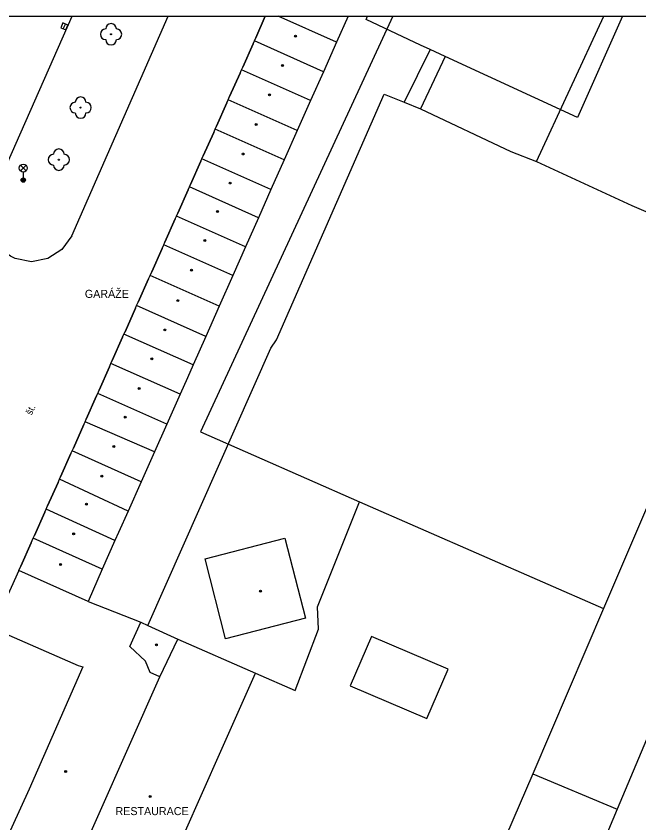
# Model space of a CAD drawing. Extents: x -596024 to -594475, y -1163820 to -1161957.
# Drawn here: x -595647.8 to -595589.5, y -1162032.5 to -1161956.9 of the extents above; entities that cross this region are included whole.
import ezdxf

# ---------------------------------------------------------------- set-up
doc = ezdxf.new("R2010")
doc.units = 0
for name, color, linetype in [('Level 10', 7, 'Continuous'), ('Level 11', 7, 'Continuous'), ('Level 22', 7, 'Continuous'), ('Level 27', 7, 'Continuous'), ('Level 33', 7, 'Continuous'), ('Level 39', 7, 'Continuous'), ('Level 40', 7, 'Continuous'), ('Level 41', 7, 'Continuous'), ('Level 5', 7, 'Continuous'), ('Level 6', 7, 'Continuous'), ('Level 7', 7, 'Continuous'), ('Vrstva 63', 7, 'Continuous')]:
    doc.layers.add(name, color=color, linetype=linetype)

msp = doc.modelspace()

# ---------------------------------------------------------------- linework, layer by layer
at = {"layer": 'Level 10'}
for p, q in [((-595650.28, -1161974.39), (-595642.564, -1161956.88)), ((-595642.59, -1161977.48), (-595633.561, -1161956.88))]:
    msp.add_line(p, q, dxfattribs=at)
msp.add_lwpolyline([(-595642.59, -1161977.48), (-595643.51, -1161978.75), (-595644.83, -1161979.59), (-595646.37, -1161979.89), (-595647.9, -1161979.59), (-595648.34, -1161979.38), (-595649.22, -1161978.74), (-595650.13, -1161977.46), (-595650.5, -1161975.94), (-595650.28, -1161974.39)], dxfattribs=at)
at = {"layer": 'Level 11'}
for p, q in [((-595615, -1161957.19), (-595614.862, -1161956.88)), ((-595599.04, -1161970.51), (-595592.74, -1161956.88))]:
    msp.add_line(p, q, dxfattribs=at)
for points in [[(-595612.513, -1161956.88), (-595630.53, -1161995.84), (-595615.63, -1162002.38), (-595592.77, -1162012.4)], [(-595590.97, -1161956.88), (-595595.2, -1161966.37), (-595607.6, -1161960.65)], [(-595609.02, -1161960), (-595609.9, -1161959.59), (-595615, -1161957.19)], [(-595609.02, -1161960), (-595611.45, -1161964.95)], [(-595607.6, -1161960.65), (-595609.02, -1161960)], [(-595607.6, -1161960.65), (-595609.9, -1161965.58)], [(-595623.92, -1161988), (-595623.41, -1161987.22), (-595613.31, -1161964.2), (-595611.45, -1161964.95)], [(-595611.45, -1161964.95), (-595609.9, -1161965.58)], [(-595609.9, -1161965.58), (-595601.46, -1161969.58), (-595599.04, -1161970.51), (-595590.11, -1161974.62), (-595578.69, -1161979.52), (-595592.77, -1162012.4), (-595599.4, -1162027.88), (-595603.12, -1162036.57)], [(-595635.47, -1162013.97), (-595623.92, -1161988)], [(-595625.37, -1162018.45), (-595621.67, -1162020.07), (-595619.47, -1162014.34), (-595619.57, -1162012.22), (-595615.63, -1162002.38)], [(-595614.49, -1162015.02), (-595616.5, -1162019.65), (-595609.31, -1162022.71)], [(-595609.31, -1162022.71), (-595607.31, -1162018.08), (-595614.49, -1162015.02)], [(-595599.4, -1162027.88), (-595591.49, -1162031.19)]]:
    msp.add_lwpolyline(points, dxfattribs=at)
at = {"layer": 'Level 22'}
for centre in [(-595638.91, -1161958.58), (-595641.76, -1161965.45), (-595643.8, -1161970.33)]:
    msp.add_circle(centre, 0.05, dxfattribs=at)
for centre, start, end in [((-595638.91, -1161958.08), 0, 180), ((-595639.41, -1161958.58), 90, 270), ((-595638.41, -1161958.58), 270, 90), ((-595638.91, -1161959.08), 180, 0), ((-595641.76, -1161964.95), 0, 180), ((-595642.26, -1161965.45), 90, 270), ((-595641.26, -1161965.45), 270, 90), ((-595641.76, -1161965.95), 180, 0), ((-595644.3, -1161970.33), 90, 270), ((-595643.8, -1161969.83), 0, 180), ((-595643.3, -1161970.33), 270, 90), ((-595643.8, -1161970.83), 180, 0)]:
    msp.add_arc(centre, 0.5, start, end, dxfattribs=at)
at = {"layer": 'Level 27'}
msp.add_line((-595643.38, -1161958.079), (-595643.18, -1161957.621), dxfattribs=at)
msp.add_lwpolyline([(-595643.151, -1161958.179), (-595642.951, -1161957.721), (-595643.409, -1161957.521), (-595643.609, -1161957.979)], close=True, dxfattribs=at)
at = {"layer": 'Level 33'}
for p, q in [((-595647.395, -1161971.38), (-595646.865, -1161970.85)), ((-595647.395, -1161970.85), (-595646.865, -1161971.38)), ((-595647.13, -1161971.49), (-595647.13, -1161972.24))]:
    msp.add_line(p, q, dxfattribs=at)
for centre, radius in [((-595647.13, -1161971.115), 0.375), ((-595647.13, -1161972.24), 0.2), ((-595647.13, -1161972.24), 0.145), ((-595647.13, -1161972.24), 0.0876)]:
    msp.add_circle(centre, radius, dxfattribs=at)
at = {"layer": 'Level 39'}
for centre, radius in [((-595621.63, -1161958.76), 0.09), ((-595621.63, -1161958.76), 0.0398), ((-595622.85, -1161961.5), 0.09), ((-595622.85, -1161961.5), 0.0398), ((-595624.07, -1161964.26), 0.09), ((-595624.07, -1161964.26), 0.0398), ((-595625.3, -1161967.03), 0.09), ((-595625.3, -1161967.03), 0.0398), ((-595626.53, -1161969.8), 0.09), ((-595626.53, -1161969.8), 0.0398), ((-595627.74, -1161972.52), 0.09), ((-595627.74, -1161972.52), 0.0398), ((-595628.93, -1161975.19), 0.09), ((-595628.93, -1161975.19), 0.0398), ((-595630.13, -1161977.9), 0.09), ((-595630.13, -1161977.9), 0.0398), ((-595631.37, -1161980.68), 0.09), ((-595631.37, -1161980.68), 0.0398), ((-595632.64, -1161983.54), 0.09), ((-595632.64, -1161983.54), 0.0398), ((-595633.86, -1161986.29), 0.09), ((-595633.86, -1161986.29), 0.0398), ((-595635.08, -1161988.99), 0.09), ((-595635.08, -1161988.99), 0.0398), ((-595636.28, -1161991.78), 0.09), ((-595636.28, -1161991.78), 0.0398), ((-595637.57, -1161994.45), 0.09), ((-595637.57, -1161994.45), 0.0398), ((-595638.64, -1161997.22), 0.09), ((-595638.64, -1161997.22), 0.0398), ((-595639.77, -1161999.99), 0.09), ((-595639.77, -1161999.99), 0.0398), ((-595641.22, -1162002.62), 0.09), ((-595641.22, -1162002.62), 0.0398), ((-595642.41, -1162005.39), 0.09), ((-595642.41, -1162005.39), 0.0398), ((-595643.63, -1162008.27), 0.09), ((-595643.63, -1162008.27), 0.0398), ((-595624.91, -1162010.76), 0.09), ((-595624.91, -1162010.76), 0.0398), ((-595634.66, -1162015.8), 0.09), ((-595634.66, -1162015.8), 0.0398), ((-595643.16, -1162027.67), 0.09), ((-595643.16, -1162027.67), 0.0398), ((-595635.24, -1162030.01), 0.09), ((-595635.24, -1162030.01), 0.0398)]:
    msp.add_circle(centre, radius, dxfattribs=at)
at = {"layer": 'Level 5'}
for p, q in [((-595625.35, -1161958.92), (-595624.451, -1161956.88)), ((-595617.77, -1161959.31), (-595623.237, -1161956.88)), ((-595616.685, -1161956.88), (-595617.77, -1161959.31))]:
    msp.add_line(p, q, dxfattribs=at)
for points in [[(-595625.6, -1161959.47), (-595625.48, -1161959.21)], [(-595625.48, -1161959.21), (-595625.35, -1161958.92)], [(-595619, -1161962.09), (-595625.48, -1161959.21)], [(-595617.77, -1161959.31), (-595619, -1161962.09)], [(-595626.57, -1161961.66), (-595625.6, -1161959.47)], [(-595626.69, -1161961.92), (-595626.57, -1161961.66)], [(-595627.8, -1161964.42), (-595626.82, -1161962.23)], [(-595626.82, -1161962.23), (-595626.69, -1161961.92)], [(-595620.21, -1161964.8), (-595626.69, -1161961.92)], [(-595619, -1161962.09), (-595620.21, -1161964.8)], [(-595627.93, -1161964.72), (-595627.8, -1161964.42)], [(-595629.03, -1161967.19), (-595628.06, -1161965)], [(-595628.06, -1161965), (-595627.93, -1161964.72)], [(-595621.46, -1161967.6), (-595627.93, -1161964.72)], [(-595620.21, -1161964.8), (-595621.46, -1161967.6)], [(-595629.29, -1161967.77), (-595629.15, -1161967.46)], [(-595629.15, -1161967.46), (-595629.03, -1161967.19)], [(-595622.67, -1161970.34), (-595629.15, -1161967.46)], [(-595621.46, -1161967.6), (-595622.67, -1161970.34)], [(-595630.26, -1161969.96), (-595629.29, -1161967.77)], [(-595630.4, -1161970.26), (-595630.26, -1161969.96)], [(-595631.47, -1161972.67), (-595630.49, -1161970.48)], [(-595630.49, -1161970.48), (-595630.4, -1161970.26)], [(-595623.92, -1161973.14), (-595630.4, -1161970.26)], [(-595622.67, -1161970.34), (-595623.92, -1161973.14)], [(-595631.68, -1161973.16), (-595631.57, -1161972.89)], [(-595631.57, -1161972.89), (-595631.47, -1161972.67)], [(-595625.09, -1161975.77), (-595631.57, -1161972.89)], [(-595632.66, -1161975.35), (-595631.68, -1161973.16)], [(-595623.92, -1161973.14), (-595625.09, -1161975.77)], [(-595633.86, -1161978.06), (-595632.89, -1161975.86)], [(-595632.89, -1161975.86), (-595632.77, -1161975.61)], [(-595632.77, -1161975.61), (-595632.66, -1161975.35)], [(-595626.3, -1161978.49), (-595632.77, -1161975.61)], [(-595625.09, -1161975.77), (-595626.3, -1161978.49)], [(-595634.12, -1161978.65), (-595633.97, -1161978.31)], [(-595633.97, -1161978.31), (-595633.86, -1161978.06)], [(-595627.49, -1161981.19), (-595633.97, -1161978.31)], [(-595635.1, -1161980.84), (-595634.12, -1161978.65)], [(-595626.3, -1161978.49), (-595627.49, -1161981.19)], [(-595635.39, -1161981.5), (-595635.25, -1161981.18)], [(-595635.25, -1161981.18), (-595635.1, -1161980.84)], [(-595628.77, -1161984.06), (-595635.25, -1161981.18)], [(-595627.49, -1161981.19), (-595628.77, -1161984.06)], [(-595636.37, -1161983.69), (-595635.39, -1161981.5)], [(-595637.59, -1161986.45), (-595636.62, -1161984.26)], [(-595636.62, -1161984.26), (-595636.51, -1161984.01)], [(-595636.51, -1161984.01), (-595636.37, -1161983.69)], [(-595630.03, -1161986.89), (-595636.51, -1161984.01)], [(-595628.77, -1161984.06), (-595630.03, -1161986.89)], [(-595637.7, -1161986.69), (-595637.59, -1161986.45)], [(-595638.8, -1161989.16), (-595637.82, -1161986.97)], [(-595637.82, -1161986.97), (-595637.7, -1161986.69)], [(-595631.22, -1161989.57), (-595637.7, -1161986.69)], [(-595630.03, -1161986.89), (-595631.22, -1161989.57)], [(-595639.05, -1161989.74), (-595638.92, -1161989.44)], [(-595638.92, -1161989.44), (-595638.8, -1161989.16)], [(-595632.44, -1161992.31), (-595638.92, -1161989.44)], [(-595631.22, -1161989.57), (-595631.75, -1161990.76)], [(-595640.03, -1161991.93), (-595639.05, -1161989.74)], [(-595631.75, -1161990.76), (-595632.44, -1161992.31)], [(-595641.24, -1161994.65), (-595640.26, -1161992.46)], [(-595640.26, -1161992.46), (-595640.16, -1161992.23)], [(-595640.16, -1161992.23), (-595640.03, -1161991.93)], [(-595633.68, -1161995.11), (-595640.16, -1161992.23)], [(-595632.44, -1161992.31), (-595633.68, -1161995.11)], [(-595641.46, -1161995.16), (-595641.34, -1161994.89)], [(-595641.34, -1161994.89), (-595641.24, -1161994.65)], [(-595634.84, -1161997.72), (-595641.34, -1161994.89)], [(-595642.44, -1161997.35), (-595641.46, -1161995.16)], [(-595633.68, -1161995.11), (-595634.84, -1161997.72)], [(-595643.63, -1162000.04), (-595642.66, -1161997.85)], [(-595642.66, -1161997.85), (-595642.56, -1161997.63)], [(-595642.56, -1161997.63), (-595642.44, -1161997.35)], [(-595636.08, -1162000.51), (-595642.56, -1161997.63)], [(-595634.84, -1161997.72), (-595636.08, -1162000.51)], [(-595643.73, -1162000.26), (-595643.63, -1162000.04)], [(-595644.85, -1162002.77), (-595643.87, -1162000.58)], [(-595643.87, -1162000.58), (-595643.73, -1162000.26)], [(-595637.31, -1162003.27), (-595643.73, -1162000.26)], [(-595636.08, -1162000.51), (-595637.31, -1162003.27)], [(-595645.1, -1162003.35), (-595644.99, -1162003.09)], [(-595644.99, -1162003.09), (-595644.85, -1162002.77)], [(-595638.54, -1162006.03), (-595644.99, -1162003.09)], [(-595646.08, -1162005.55), (-595645.1, -1162003.35)], [(-595637.31, -1162003.27), (-595638.2, -1162005.27)], [(-595638.2, -1162005.27), (-595638.54, -1162006.03)], [(-595647.35, -1162008.42), (-595646.38, -1162006.23)], [(-595646.38, -1162006.23), (-595646.2, -1162005.81)], [(-595646.2, -1162005.81), (-595646.08, -1162005.55)], [(-595639.73, -1162008.71), (-595646.2, -1162005.81)], [(-595638.54, -1162006.03), (-595639.73, -1162008.71)], [(-595630.08, -1162007.73), (-595622.62, -1162005.79)], [(-595622.62, -1162005.79), (-595620.69, -1162013.29)], [(-595628.18, -1162015.23), (-595630.08, -1162007.73)], [(-595647.54, -1162008.84), (-595647.35, -1162008.42)], [(-595647.54, -1162008.84), (-595650, -1162014.24)], [(-595641.06, -1162011.72), (-595647.54, -1162008.84)], [(-595639.73, -1162008.71), (-595641.06, -1162011.72)], [(-595641.06, -1162011.72), (-595636.12, -1162013.67)], [(-595637.14, -1162015.96), (-595636.12, -1162013.67)], [(-595636.12, -1162013.67), (-595635.47, -1162013.97)], [(-595620.69, -1162013.29), (-595628.18, -1162015.23)], [(-595650, -1162014.24), (-595641.99, -1162017.72)], [(-595635.47, -1162013.97), (-595632.66, -1162015.27)], [(-595634.33, -1162018.8), (-595632.66, -1162015.27)], [(-595632.66, -1162015.27), (-595625.37, -1162018.45)], [(-595635.69, -1162017.33), (-595637.14, -1162015.96)], [(-595635.25, -1162018.39), (-595635.69, -1162017.33)], [(-595641.55, -1162017.84), (-595646.57, -1162029.33)], [(-595641.99, -1162017.72), (-595641.55, -1162017.84)], [(-595642.98, -1162038.29), (-595634.33, -1162018.8)], [(-595634.33, -1162018.8), (-595635.25, -1162018.39)], [(-595628.62, -1162025.77), (-595625.37, -1162018.45)], [(-595635.48, -1162041.25), (-595628.62, -1162025.77)], [(-595646.57, -1162029.33), (-595650.83, -1162038.55)]]:
    msp.add_lwpolyline(points, dxfattribs=at)
at = {"layer": 'Level 6'}
msp.add_line((-595624.451, -1161956.88), (-595625.35, -1161958.92), dxfattribs=at)
for points in [[(-595625.6, -1161959.47), (-595626.57, -1161961.66)], [(-595626.82, -1161962.23), (-595627.8, -1161964.42)], [(-595628.06, -1161965), (-595629.03, -1161967.19)], [(-595629.29, -1161967.77), (-595630.26, -1161969.96)], [(-595630.49, -1161970.48), (-595631.47, -1161972.67)], [(-595631.68, -1161973.16), (-595632.66, -1161975.35)], [(-595632.89, -1161975.86), (-595633.86, -1161978.06)], [(-595634.12, -1161978.65), (-595635.1, -1161980.84)], [(-595635.39, -1161981.5), (-595636.37, -1161983.69)], [(-595636.62, -1161984.26), (-595637.59, -1161986.45)], [(-595637.82, -1161986.97), (-595638.8, -1161989.16)], [(-595639.05, -1161989.74), (-595640.03, -1161991.93)], [(-595640.26, -1161992.46), (-595641.24, -1161994.65)], [(-595641.46, -1161995.16), (-595642.44, -1161997.35)], [(-595642.66, -1161997.85), (-595643.63, -1162000.04)], [(-595643.87, -1162000.58), (-595644.85, -1162002.77)], [(-595645.1, -1162003.35), (-595646.08, -1162005.55)], [(-595646.38, -1162006.23), (-595647.35, -1162008.42)]]:
    msp.add_lwpolyline(points, dxfattribs=at)
at = {"layer": 'Level 7'}
msp.add_lwpolyline([(-595569.32, -1161978.01), (-595574.7, -1161991.16), (-595575.42, -1161992.99), (-595580.09, -1162004.1), (-595591.49, -1162031.19), (-595595.15, -1162039.9), (-595604.54, -1162062.22), (-595605.62, -1162064.8)], dxfattribs=at)
at = {"layer": 'Vrstva 63'}
msp.add_lwpolyline([(-594475.47, -1163820.23), (-596024.42, -1163820.23), (-596024.42, -1161956.88), (-594475.47, -1161956.88)], close=True, dxfattribs=at)

# ---------------------------------------------------------------- texts
at = {"layer": 'Level 40'}
msp.add_text('št.', height=0.65, rotation=65.13, dxfattribs=at).set_placement((-595646.35, -1161994.32))
at = {"layer": 'Level 41'}
for s, p in [('GARÁŽE', (-595641.36, -1161983.28)), ('RESTAURACE', (-595638.49, -1162031.75))]:
    msp.add_text(s, height=0.75, dxfattribs=at).set_placement(p)

doc.saveas('drawing.dxf')
